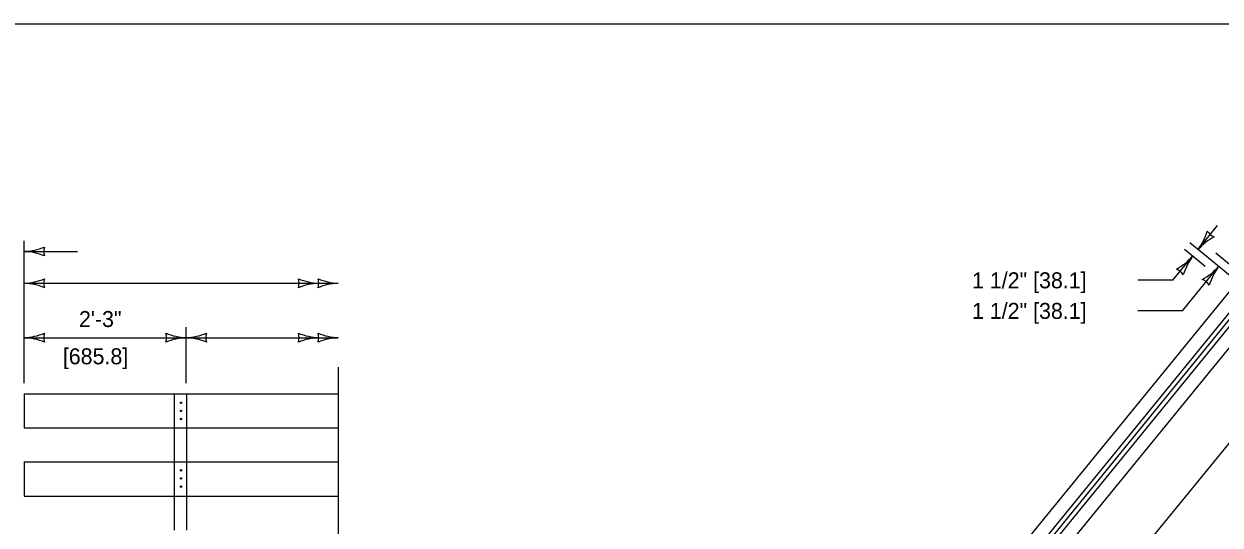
# Model space of a CAD drawing. Extents: x 49991.4 to 50021, y 49987.6 to 50011.4.
# Drawn here: x 50005.062 to 50009.55, y 49997.118 to 49998.999 of the extents above; entities that cross this region are included whole.
import ezdxf

# ---------------------------------------------------------------- set-up
doc = ezdxf.new("R2010")
doc.units = 0
for name, color, linetype in [('Level 1', 7, 'Continuous'), ('Level 2', 7, 'Continuous'), ('Level 3', 7, 'Continuous'), ('Level 4', 7, 'Continuous'), ('Level 6', 7, 'Continuous')]:
    doc.layers.add(name, color=color, linetype=linetype)

msp = doc.modelspace()

# ---------------------------------------------------------------- linework, layer by layer
at = {"layer": 'Level 1'}
for p, q in [((50007.4465, 49995.3728), (50009.6889, 49998.1205)), ((50007.5494, 49995.2888), (50009.7272, 49997.9577)), ((50007.6228, 49995.51), (50009.5947, 49997.926)), ((50007.6356, 49995.4996), (50009.6075, 49997.9156)), ((50007.6486, 49995.489), (50009.6203, 49997.9052)), ((50005.0636, 49997.6101), (50005.0636, 49997.4824)), ((50005.0636, 49997.6101), (50006.2419, 49997.6101)), ((50005.0636, 49997.4824), (50006.2419, 49997.4824)), ((50005.6278, 49997.3546), (50005.6278, 49997.4824)), ((50005.6732, 49997.3546), (50005.6732, 49997.4824)), ((50005.0636, 49997.3546), (50005.0636, 49997.2268)), ((50005.0636, 49997.3546), (50006.2419, 49997.3546)), ((50005.0636, 49997.2268), (50006.2419, 49997.2268)), ((50005.6278, 49997.099), (50005.6278, 49997.2268)), ((50005.6732, 49997.099), (50005.6732, 49997.2268))]:
    msp.add_line(p, q, dxfattribs=at)
msp.add_lwpolyline([(49999.3835, 49998.9992), (50016.7501, 49998.9992), (50016.7501, 49987.7988), (49999.3835, 49987.7988)], close=True, dxfattribs=at)
for centre in [(50005.6522, 49997.5771), (50005.6522, 49997.5464), (50005.6522, 49997.5158), (50005.6522, 49997.3234), (50005.6522, 49997.2927), (50005.6522, 49997.2621)]:
    msp.add_ellipse(centre, major_axis=(0.00285, 0), ratio=0.940299, dxfattribs=at)
at = {"layer": 'Level 3'}
for p, q in [((50009.4674, 49998.1515), (50009.541, 49998.2418)), ((50005.0636, 49997.6501), (50005.0636, 49998.1848)), ((50009.9245, 49997.7786), (50009.4364, 49998.1768)), ((50005.0636, 49998.1448), (50005.2639, 49998.1448)), ((50009.3737, 49998.0366), (50009.4474, 49998.127)), ((50009.494, 49998.0891), (50009.4164, 49998.1523)), ((50009.6219, 49998.0662), (50009.5339, 49998.1381)), ((50009.4092, 49997.9218), (50009.5449, 49998.0883)), ((50009.3737, 49998.0366), (50009.2417, 49998.0366)), ((50005.0636, 49998.0256), (50006.2419, 49998.0256)), ((50009.4092, 49997.9218), (50009.2417, 49997.9218)), ((50005.6712, 49997.6501), (50005.6712, 49997.8613)), ((50005.0636, 49997.8213), (50005.6712, 49997.8213)), ((50005.6712, 49997.8213), (50006.2419, 49997.8213)), ((50005.6712, 49997.8213), (50006.1348, 49997.8213)), ((50007.8012, 49995.24), (50009.8935, 49997.8039))]:
    msp.add_line(p, q, dxfattribs=at)
for centre, radius, start, end in [((50009.2798, 49998.2896), 0.233, 323.6452, 342.895), ((50009.5484, 49998.2509), 0.0548, 212.9567, 248.6791), ((50009.6338, 49998.0041), 0.2223, 118.2739, 138.4574), ((50005.0521, 49998.3775), 0.233, 272.8273, 292.0772), ((50005.0544, 49997.9227), 0.2223, 67.456, 87.6395), ((50005.1918, 49998.1448), 0.0548, 162.1388, 197.8612), ((50009.281, 49998.2745), 0.2223, 298.2668, 318.4503), ((50009.6351, 49997.9889), 0.233, 143.6381, 162.888), ((50009.3664, 49998.0277), 0.0548, 32.9496, 68.672), ((50009.3785, 49998.2357), 0.2223, 298.2672, 318.4507), ((50009.7325, 49997.9502), 0.233, 143.6385, 162.8883), ((50005.0521, 49998.2583), 0.233, 272.8273, 292.0772), ((50005.1918, 49998.0256), 0.0548, 162.1388, 197.8612), ((50006.1776, 49998.2477), 0.2223, 247.456, 267.6395), ((50006.0402, 49998.0256), 0.0548, 342.1388, 17.8612), ((50006.2511, 49998.2477), 0.2223, 247.456, 267.6395), ((50006.1137, 49998.0256), 0.0548, 342.1388, 17.8612), ((50009.4639, 49997.9889), 0.0548, 32.95, 68.6724), ((50005.0544, 49997.8035), 0.2223, 67.456, 87.6395), ((50006.18, 49997.7929), 0.233, 92.8273, 112.0772), ((50006.2534, 49997.7929), 0.233, 92.8273, 112.0772), ((50005.0521, 49998.054), 0.233, 272.8273, 292.0772), ((50005.0544, 49997.5992), 0.2223, 67.456, 87.6395), ((50005.1918, 49997.8213), 0.0548, 162.1388, 197.8612), ((50005.6804, 49998.0434), 0.2223, 247.456, 267.6395), ((50005.543, 49997.8213), 0.0548, 342.1388, 17.8612), ((50005.6827, 49997.5886), 0.233, 92.8273, 112.0772), ((50005.6597, 49998.054), 0.233, 272.8273, 292.0772), ((50005.662, 49997.5992), 0.2223, 67.456, 87.6395), ((50005.7994, 49997.8213), 0.0548, 162.1388, 197.8612), ((50006.1776, 49998.0434), 0.2223, 247.456, 267.6395), ((50006.0402, 49997.8213), 0.0548, 342.1388, 17.8612), ((50006.18, 49997.5886), 0.233, 92.8273, 112.0772), ((50006.2511, 49998.0434), 0.2223, 247.456, 267.6395), ((50006.1137, 49997.8213), 0.0548, 342.1388, 17.8612), ((50006.2534, 49997.5886), 0.233, 92.8273, 112.0772)]:
    msp.add_arc(centre, radius, start, end, dxfattribs=at)
at = {"layer": 'Level 4'}
for p, q in [((50005.6278, 49997.4824), (50005.6278, 49997.6101)), ((50005.6732, 49997.4824), (50005.6732, 49997.6101)), ((50005.6278, 49997.2268), (50005.6278, 49997.3546)), ((50005.6732, 49997.2268), (50005.6732, 49997.3546))]:
    msp.add_line(p, q, dxfattribs=at)
at = {"layer": 'Level 6'}
msp.add_line((50006.2419, 49997.7101), (50006.2419, 49996.2052), dxfattribs=at)

# ---------------------------------------------------------------- texts
at = {"layer": 'Level 2'}
for s, p in [('1 1/2" [38.1]', (50008.6196, 49998.0066)), ('1 1/2" [38.1]', (50008.6196, 49997.8918)), ('2\'-3"', (50005.2689, 49997.8613)), ('[685.8]', (50005.2084, 49997.7213))]:
    msp.add_text(s, height=0.06, dxfattribs=at).set_placement(p)

doc.saveas('drawing.dxf')
